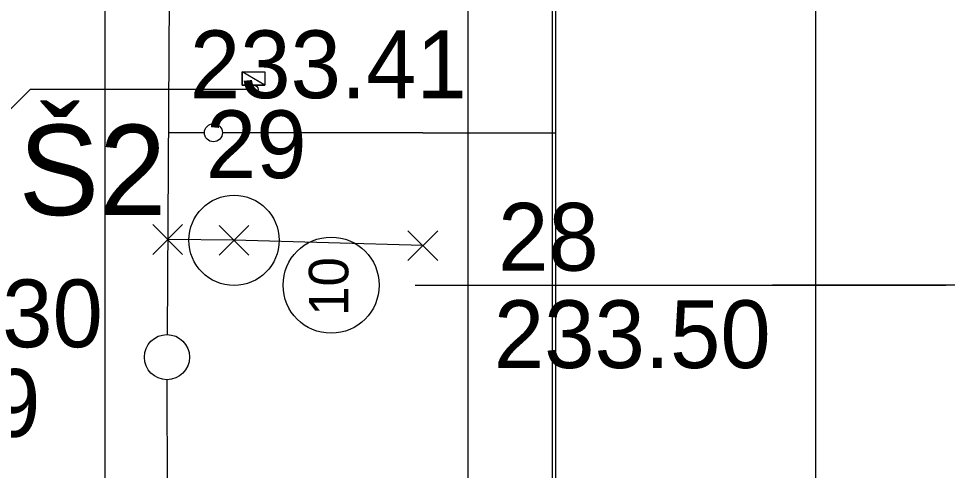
# Model space of a CAD drawing. Extents: x -264031 to -263588, y -1242281 to -1242059.
# Drawn here: x -263926.05 to -263905.47, y -1242143.98 to -1242133.98 of the extents above; entities that cross this region are included whole.
import ezdxf

# ---------------------------------------------------------------- set-up
doc = ezdxf.new("R2010")
doc.units = 0
for name, color, linetype in [('HESCON_OSI_STAVBY_KFA', 7, 'Continuous'), ('KFA_2D_SITUACIA_DSP', 7, 'Continuous'), ('KFA_BODY_CISLO', 7, 'Continuous'), ('KFA_BODY_SYMBOL', 7, 'Continuous'), ('KFA_BODY_VYSKA', 7, 'Continuous'), ('KFA_JESTV_IS_DSP_-_KANAL_SPLASK', 7, 'Continuous'), ('KFA_SO-40-1-II_SK_MER_TRIBUNA_A', 7, 'Continuous'), ('POPIS', 7, 'Continuous')]:
    doc.layers.add(name, color=color, linetype=linetype)

msp = doc.modelspace()

# ---------------------------------------------------------------- linework, layer by layer
at = {"layer": 'HESCON_OSI_STAVBY_KFA'}
for p, q in [((-263908.393, -1242083.237), (-263908.393, -1242246.707)), ((-263917.265, -1242139.882), (-263905.505, -1242139.882)), ((-263917.265, -1242139.882), (-263905.505, -1242139.882)), ((-263792.653, -1242139.882), (-263909.343, -1242139.882))]:
    msp.add_line(p, q, dxfattribs=at)
msp.add_circle((-263919.125, -1242139.882), 1.064, dxfattribs=at)
at = {"layer": 'KFA_2D_SITUACIA_DSP'}
for p, q in [((-263924.143, -1242082.64), (-263924.143, -1242185.14)), ((-263914.218, -1242196.332), (-263914.218, -1242132.432)), ((-263921.093, -1242135.452), (-263921.093, -1242135.162)), ((-263921.093, -1242135.162), (-263920.593, -1242135.162)), ((-263920.593, -1242135.452), (-263921.093, -1242135.162)), ((-263920.593, -1242135.452), (-263921.093, -1242135.162)), ((-263921.093, -1242135.162), (-263921.093, -1242135.452)), ((-263920.593, -1242135.162), (-263920.593, -1242135.452)), ((-263920.593, -1242135.452), (-263921.093, -1242135.452)), ((-263921.093, -1242135.452), (-263920.593, -1242135.452)), ((-263925.797, -1242135.552), (-263926.592, -1242136.347)), ((-263920.943, -1242135.552), (-263925.797, -1242135.552)), ((-263921.932, -1242136.507), (-263922.732, -1242136.507)), ((-263917.093, -1242136.507), (-263921.532, -1242136.507)), ((-263917.093, -1242136.507), (-263914.143, -1242136.507))]:
    msp.add_line(p, q, dxfattribs=at)
msp.add_lwpolyline([(-263794.893, -1242227.382), (-263808.968, -1242241.457), (-263894.968, -1242241.457), (-263909.043, -1242227.382), (-263909.043, -1242196.333), (-263914.143, -1242196.333), (-263914.143, -1242132.433), (-263909.043, -1242132.433), (-263909.043, -1242101.382), (-263894.968, -1242087.307), (-263808.968, -1242087.307), (-263794.893, -1242101.382), (-263794.893, -1242227.382)], dxfattribs=at)
msp.add_lwpolyline([(-263893.618, -1242118.282), (-263916.093, -1242118.282), (-263916.093, -1242175.482), (-263914.293, -1242175.482), (-263914.293, -1242210.482), (-263893.618, -1242210.482), (-263893.618, -1242166.382), (-263900.043, -1242166.382), (-263900.043, -1242162.382), (-263893.618, -1242162.382)], close=True, dxfattribs=at)
for centre, radius in [((-263920.843, -1242135.552), 0.1), ((-263921.732, -1242136.507), 0.2)]:
    msp.add_circle(centre, radius, dxfattribs=at)
at = {"layer": 'KFA_BODY_SYMBOL'}
for p, q in [((-263923.079, -1242139.204), (-263922.416, -1242138.542)), ((-263922.416, -1242139.204), (-263923.079, -1242138.542)), ((-263921.609, -1242139.221), (-263920.946, -1242138.558)), ((-263920.946, -1242139.221), (-263921.609, -1242138.558)), ((-263917.425, -1242139.339), (-263916.762, -1242138.676)), ((-263916.762, -1242139.339), (-263917.425, -1242138.676))]:
    msp.add_line(p, q, dxfattribs=at)
at = {"layer": 'KFA_JESTV_IS_DSP_-_KANAL_SPLASK'}
for p, q in [((-263922.558, -1242109.317), (-263922.76, -1242140.975)), ((-263922.763, -1242141.975), (-263922.734, -1242183.174))]:
    msp.add_line(p, q, dxfattribs=at)
msp.add_circle((-263922.763, -1242141.475), 0.5, dxfattribs=at)
at = {"layer": 'KFA_SO-40-1-II_SK_MER_TRIBUNA_A'}
msp.add_lwpolyline([(-263917.093, -1242139.007), (-263921.277, -1242138.889), (-263922.747, -1242138.873)], dxfattribs=at)
msp.add_circle((-263921.277, -1242138.889), 1, dxfattribs=at)

# ---------------------------------------------------------------- texts
at = {"layer": 'HESCON_OSI_STAVBY_KFA'}
msp.add_text('10', height=0.875, rotation=90, dxfattribs=at).set_placement((-263918.744, -1242140.562))
at = {"layer": 'KFA_BODY_CISLO'}
for s, p in [('29', (-263921.9, -1242137.512)), ('28', (-263915.426, -1242139.561)), ('30', (-263926.414, -1242141.256))]:
    msp.add_text(s, height=1.5, dxfattribs=at).set_placement(p)
at = {"layer": 'KFA_BODY_VYSKA'}
for s, p in [('233.41', (-263922.254, -1242135.742)), ('233.50', (-263915.519, -1242141.717)), ('233.39', (-263931.701, -1242143.239))]:
    msp.add_text(s, height=1.5, dxfattribs=at).set_placement(p)
at = {"layer": 'POPIS'}
msp.add_text('Š2', height=2, dxfattribs=at).set_placement((-263926.05, -1242138.33))

doc.saveas('drawing.dxf')
